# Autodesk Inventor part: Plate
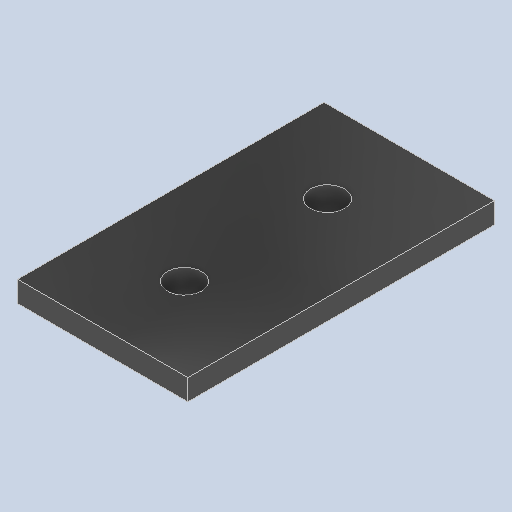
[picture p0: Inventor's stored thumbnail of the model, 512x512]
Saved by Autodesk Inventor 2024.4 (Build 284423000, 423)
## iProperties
Created: 2025-07
Part Number: Plate
Material: Generic
Document SubType Name: Modeling
Designer: AdminForWorker
Density: 1 g/cm^3
Appearance: Default
Title: Plate v1
Author: AdminForWorker
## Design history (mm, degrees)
feature "Body1"
body "Solid1"
